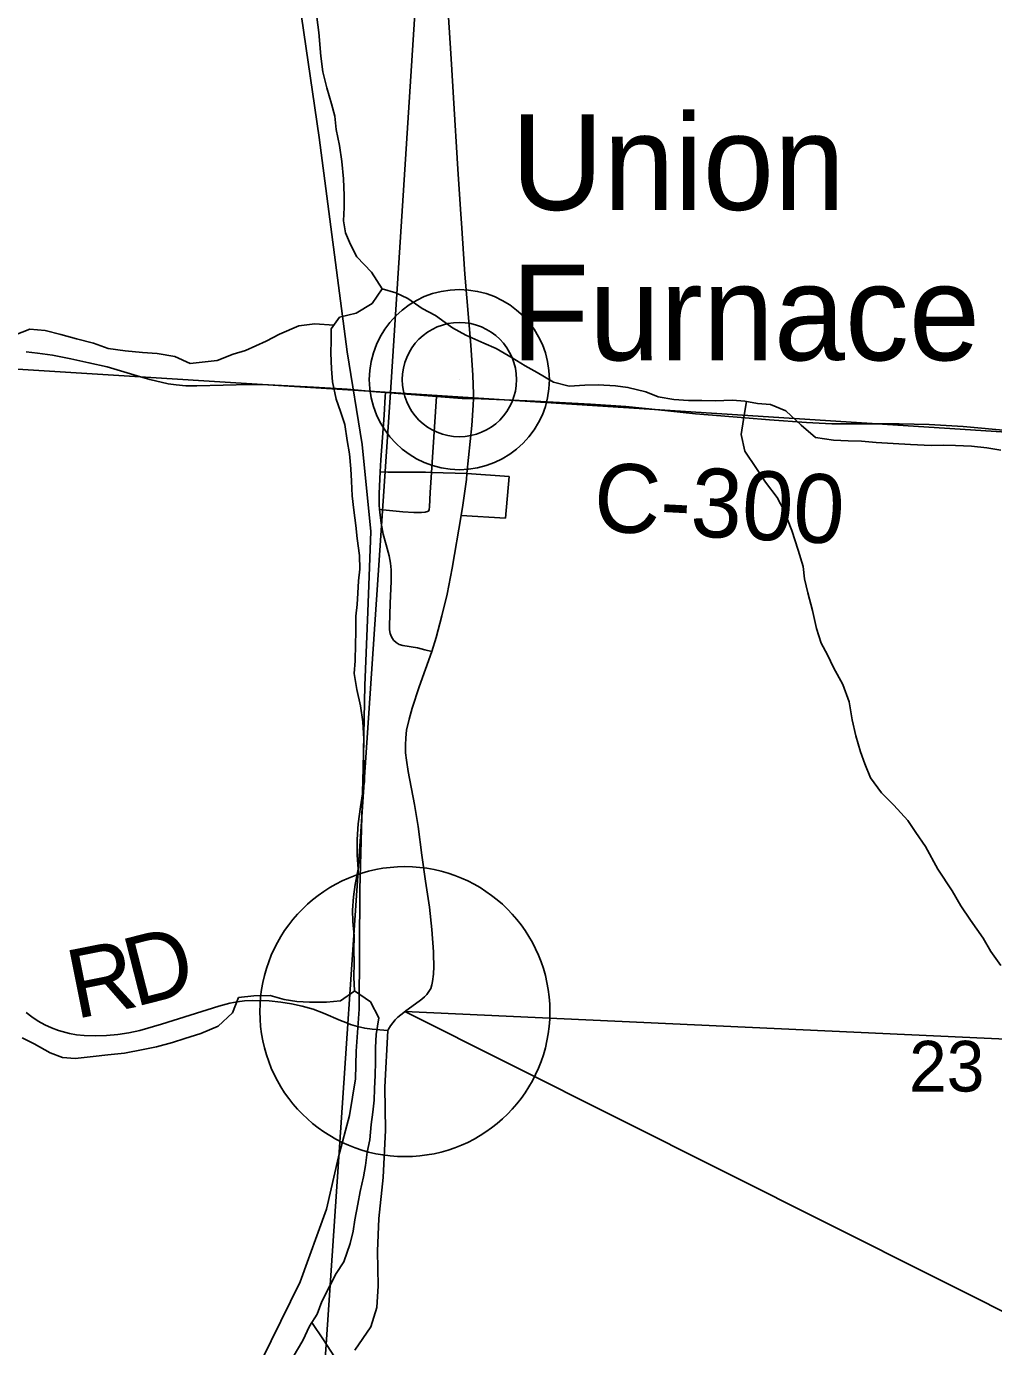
# Model space of a CAD drawing. Extents: x 0 to 34, y 0 to 22.
# Drawn here: x 5.158 to 5.957, y 17.019 to 18.11 of the extents above; entities that cross this region are included whole.
import ezdxf

# ---------------------------------------------------------------- set-up
doc = ezdxf.new("R2010")
doc.units = 0
for name, color, linetype in [('Default', 7, 'Continuous'), ('GM_X_Corporation', 7, 'Continuous'), ('GM_X_County_Road', 7, 'Continuous'), ('GM_X_County_Road_Text', 7, 'Continuous'), ('GM_X_Minor_River', 7, 'Continuous'), ('GM_X_Rail_Line', 7, 'Continuous'), ('GM_X_Section_Text', 7, 'Continuous'), ('GM_X_State_Route', 7, 'Continuous'), ('GM_X_Township_Road', 7, 'Continuous'), ('GM_X_Township_Road_Text', 7, 'Continuous'), ('GM_X_Unincorporated', 7, 'Continuous'), ('GM_X_Unincorporated_Location', 7, 'Continuous'), ('GM_X_Unincorporated_Text', 7, 'Continuous'), ('SH_Text', 7, 'Continuous')]:
    doc.layers.add(name, color=color, linetype=linetype)

msp = doc.modelspace()

# ---------------------------------------------------------------- linework, layer by layer
at = {"layer": 'Default'}
msp.add_circle((5.4711, 17.2956), 0.1198, dxfattribs=at)
at = {"layer": 'GM_X_Corporation'}
for points in [[(4.5309, 18.9179), (5.5263, 18.8526), (5.4592, 17.8072), (4.4596, 17.8697), (4.5247, 18.9179)], [(6.5391, 18.7835), (6.4386, 17.7441), (5.4592, 17.8072), (5.5263, 18.8526)], [(4.4596, 17.8697), (5.4592, 17.8072), (5.3901, 16.7843), (4.3853, 16.8539)], [(6.4386, 17.7441), (6.3912, 16.7203), (5.3901, 16.7843), (5.4592, 17.8072)]]:
    msp.add_lwpolyline(points, close=True, dxfattribs=at)
at = {"layer": 'GM_X_County_Road'}
for points in [[(5.1583, 17.8407), (5.1676, 17.8397), (5.1799, 17.8379), (5.195, 17.835), (5.2101, 17.8317), (5.2251, 17.8282), (5.2498, 17.8207), (5.2604, 17.8177), (5.2756, 17.8142), (5.2821, 17.8133), (5.2902, 17.8127), (5.2993, 17.8126), (5.3428, 17.8137), (5.3583, 17.8135), (5.3956, 17.8116), (5.419, 17.81), (5.4235, 17.8097), (5.4473, 17.8077)], [(5.4473, 17.8077), (5.4512, 17.8074), (5.4551, 17.8071), (5.4938, 17.804), (5.4973, 17.8037), (5.5185, 17.8022), (5.5216, 17.8022), (5.5277, 17.8021)], [(5.5277, 17.8021), (5.5781, 17.8), (5.6245, 17.7974), (5.6536, 17.7954), (5.6806, 17.7927), (5.7113, 17.7895), (5.732, 17.7877), (5.7722, 17.7846), (5.803, 17.7822), (5.8239, 17.7811), (5.8577, 17.7812), (5.8794, 17.7813), (5.9043, 17.7807), (5.9322, 17.7789), (5.9713, 17.7755)]]:
    msp.add_lwpolyline(points, dxfattribs=at)
at = {"layer": 'GM_X_Minor_River'}
for p, q in [((5.1612, 17.8595), (5.1487, 17.8544)), ((5.174, 17.8584), (5.1612, 17.8595)), ((5.1869, 17.8551), (5.174, 17.8584)), ((5.1998, 17.8515), (5.1869, 17.8551)), ((5.3674, 17.8553), (5.3565, 17.8495)), ((5.3836, 17.8622), (5.3674, 17.8553)), ((5.3968, 17.8639), (5.3836, 17.8622)), ((5.4124, 17.8628), (5.3968, 17.8639)), ((5.2139, 17.8478), (5.1998, 17.8515)), ((5.226, 17.8434), (5.2139, 17.8478)), ((5.24, 17.8416), (5.226, 17.8434)), ((5.3565, 17.8495), (5.3395, 17.8418)), ((5.2544, 17.8402), (5.24, 17.8416)), ((5.2665, 17.8392), (5.2544, 17.8402)), ((5.2809, 17.8367), (5.2665, 17.8392)), ((5.2938, 17.8311), (5.2809, 17.8367)), ((5.3037, 17.832), (5.2938, 17.8311)), ((5.3161, 17.8336), (5.3037, 17.832)), ((5.3293, 17.8386), (5.3161, 17.8336)), ((5.3395, 17.8418), (5.3293, 17.8386)), ((5.7532, 17.7998), (5.7509, 17.7849)), ((5.7509, 17.7849), (5.7488, 17.7723)), ((5.7488, 17.7723), (5.7519, 17.7587)), ((5.7519, 17.7587), (5.7615, 17.7444)), ((5.7615, 17.7444), (5.7691, 17.7331)), ((5.7691, 17.7331), (5.7787, 17.7203)), ((5.7787, 17.7203), (5.7841, 17.7098)), ((5.7841, 17.7098), (5.7907, 17.6931)), ((5.7907, 17.6931), (5.7961, 17.6769)), ((5.7961, 17.6769), (5.8, 17.6633)), ((5.8, 17.6633), (5.8012, 17.6531)), ((5.8012, 17.6531), (5.804, 17.6417)), ((5.804, 17.6417), (5.8079, 17.627)), ((5.8079, 17.627), (5.8111, 17.6122)), ((5.8111, 17.6122), (5.815, 17.6001)), ((5.815, 17.6001), (5.8203, 17.5903)), ((5.8203, 17.5903), (5.8253, 17.5798)), ((5.8253, 17.5798), (5.833, 17.5658)), ((5.833, 17.5658), (5.8381, 17.5515)), ((5.8381, 17.5515), (5.8405, 17.5367)), ((5.8405, 17.5367), (5.8436, 17.5235)), ((5.8436, 17.5235), (5.8475, 17.5102)), ((5.8475, 17.5102), (5.851, 17.5004)), ((5.851, 17.5004), (5.8557, 17.4887)), ((5.8557, 17.4887), (5.8648, 17.4763)), ((5.8648, 17.4763), (5.8751, 17.4662)), ((5.8751, 17.4662), (5.8866, 17.4534)), ((5.8866, 17.4534), (5.8931, 17.4436)), ((5.8931, 17.4436), (5.9012, 17.4319)), ((5.9012, 17.4319), (5.9115, 17.4134)), ((5.9115, 17.4134), (5.9231, 17.3954)), ((5.9231, 17.3954), (5.9304, 17.3829)), ((5.9304, 17.3829), (5.9384, 17.3712)), ((5.9384, 17.3712), (5.9487, 17.3562)), ((5.9487, 17.3562), (5.9553, 17.3453)), ((5.9553, 17.3453), (5.9633, 17.3336)), ((5.3464, 17.3086), (5.3336, 17.3074)), ((5.3597, 17.3088), (5.3464, 17.3086)), ((5.3714, 17.3055), (5.3597, 17.3088)), ((5.4297, 17.3128), (5.418, 17.3044)), ((5.3336, 17.3074), (5.3288, 17.2945)), ((5.3817, 17.304), (5.3714, 17.3055)), ((5.3923, 17.3034), (5.3817, 17.304)), ((5.4063, 17.3035), (5.3923, 17.3034)), ((5.418, 17.3044), (5.4063, 17.3035)), ((5.3288, 17.2945), (5.3168, 17.2837)), ((5.3024, 17.2775), (5.2892, 17.2733)), ((5.3168, 17.2837), (5.3024, 17.2775)), ((5.1648, 17.2691), (5.1549, 17.2739)), ((5.1781, 17.2616), (5.1648, 17.2691)), ((5.2658, 17.2666), (5.2549, 17.2642)), ((5.279, 17.2701), (5.2658, 17.2666)), ((5.2892, 17.2733), (5.279, 17.2701)), ((5.1883, 17.2576), (5.1781, 17.2616)), ((5.1986, 17.2569), (5.1883, 17.2576)), ((5.2137, 17.2586), (5.1986, 17.2569)), ((5.2258, 17.2598), (5.2137, 17.2586)), ((5.2394, 17.2614), (5.2258, 17.2598)), ((5.2549, 17.2642), (5.2394, 17.2614)), ((5.3942, 17.0387), (5.4038, 17.0246)), ((5.4038, 17.0246), (5.413, 17.0103))]:
    msp.add_line(p, q, dxfattribs=at)
for points in [[(5.3984, 18.117), (5.4, 18.1045), (5.4017, 18.0848), (5.4034, 18.072), (5.4065, 18.0587), (5.4104, 18.0455), (5.4131, 18.0353), (5.4144, 18.0243), (5.4171, 18.0111), (5.4191, 17.9978), (5.4204, 17.9835), (5.4209, 17.9698), (5.421, 17.96), (5.4203, 17.949), (5.4219, 17.9391), (5.4262, 17.9293), (5.4315, 17.9191), (5.4434, 17.9064), (5.4522, 17.8928), (5.444, 17.8806), (5.4308, 17.8725), (5.4172, 17.8694), (5.4101, 17.8598), (5.4102, 17.85), (5.4099, 17.8397), (5.4104, 17.8265), (5.4113, 17.8159), (5.4144, 17.8015), (5.4179, 17.7913), (5.4214, 17.7807), (5.4234, 17.7675), (5.4254, 17.7565), (5.4263, 17.744), (5.4271, 17.7338), (5.4276, 17.7217), (5.4288, 17.7099), (5.4305, 17.6971), (5.4317, 17.6865), (5.4337, 17.6725), (5.4338, 17.6611), (5.4327, 17.6516), (5.4321, 17.6414), (5.4318, 17.6319), (5.4307, 17.6224), (5.4305, 17.6091), (5.4302, 17.5993), (5.4299, 17.5853), (5.4292, 17.575), (5.4313, 17.5618), (5.4344, 17.5482), (5.4364, 17.5349), (5.4373, 17.5209), (5.437, 17.5061), (5.4375, 17.4955), (5.4376, 17.4853), (5.4362, 17.4754), (5.4344, 17.4648), (5.4326, 17.4508), (5.4316, 17.4379), (5.4317, 17.425)], [(5.4522, 17.8928), (5.4636, 17.8895), (5.4735, 17.8847), (5.4853, 17.8764), (5.4963, 17.8708), (5.5104, 17.8604), (5.5214, 17.8544), (5.5362, 17.8477), (5.5465, 17.8433), (5.5598, 17.8358), (5.5704, 17.8291), (5.5803, 17.8235), (5.594, 17.8156), (5.6069, 17.8124), (5.6198, 17.8132), (5.6307, 17.8133), (5.6451, 17.8127), (5.6553, 17.8113), (5.6701, 17.8076), (5.6804, 17.8035), (5.6933, 17.8014), (5.7054, 17.8004), (5.7163, 17.8005), (5.7273, 17.8002), (5.7417, 17.8007), (5.7519, 17.8), (5.7625, 17.7979), (5.7731, 17.7972), (5.7857, 17.792), (5.7986, 17.78), (5.8104, 17.7699), (5.8252, 17.7677), (5.8373, 17.7671), (5.8483, 17.7668), (5.8604, 17.7658), (5.8744, 17.7648), (5.8888, 17.7641), (5.9059, 17.7632), (5.9161, 17.7636), (5.9259, 17.7633), (5.9392, 17.7627), (5.952, 17.7613), (5.9634, 17.7595)], [(5.4317, 17.425), (5.4325, 17.4133), (5.43, 17.4007), (5.4286, 17.3905), (5.4279, 17.3795), (5.428, 17.37), (5.4292, 17.3583), (5.429, 17.3465), (5.4291, 17.3363), (5.4288, 17.3242), (5.4296, 17.3128), (5.4426, 17.3038), (5.4495, 17.2906), (5.4474, 17.2766), (5.4467, 17.266), (5.4468, 17.2542), (5.4465, 17.2432), (5.4459, 17.2319), (5.4456, 17.2224), (5.4445, 17.2125), (5.4431, 17.2023), (5.4421, 17.1898), (5.4399, 17.1795), (5.4385, 17.1685), (5.437, 17.159), (5.4341, 17.1469), (5.4323, 17.1366), (5.4298, 17.1237), (5.4283, 17.1142), (5.4258, 17.104), (5.4206, 17.0888), (5.4143, 17.0792), (5.4091, 17.069), (5.4024, 17.056), (5.3987, 17.0458), (5.3923, 17.0358), (5.3867, 17.024), (5.3789, 17.0103)]]:
    msp.add_lwpolyline(points, dxfattribs=at)
at = {"layer": 'GM_X_Rail_Line'}
msp.add_lwpolyline([(5.3526, 17.0073), (5.3847, 17.0725), (5.4062, 17.1325), (5.4163, 17.1756), (5.4252, 17.2099), (5.4302, 17.24), (5.4309, 17.2629), (5.4333, 17.2975), (5.4338, 17.3964), (5.4367, 17.4966), (5.4381, 17.5651), (5.4404, 17.626), (5.443, 17.6922), (5.4357, 17.7642), (5.4234, 17.8408), (5.4004, 18.0178), (5.3565, 18.3179)], dxfattribs=at)
at = {"layer": 'GM_X_State_Route'}
for points in [[(5.5112, 18.0505), (5.5095, 18.0784), (5.5026, 18.1868), (5.496, 18.2766), (5.4945, 18.2921), (5.4928, 18.3043), (5.4911, 18.3134), (5.4889, 18.3224), (5.4881, 18.3254), (5.4872, 18.3284)], [(5.4947, 17.343), (5.4947, 17.3451), (5.4934, 17.3634), (5.4914, 17.3819), (5.4882, 17.4034), (5.4852, 17.4249), (5.4821, 17.4485), (5.4791, 17.4666), (5.4737, 17.494), (5.4723, 17.5032), (5.4717, 17.5094), (5.4716, 17.5156), (5.4718, 17.5219), (5.4725, 17.5281), (5.4745, 17.5373), (5.477, 17.5463), (5.4829, 17.564), (5.4933, 17.5931), (5.497, 17.6048), (5.5017, 17.6225), (5.5059, 17.6406), (5.5101, 17.6619), (5.5176, 17.7054), (5.519, 17.7139), (5.5219, 17.7353), (5.5224, 17.7401), (5.5264, 17.7799), (5.5276, 17.7965), (5.5277, 17.8021), (5.5278, 17.8057), (5.5272, 17.8213), (5.5256, 17.8461), (5.5207, 17.9048), (5.5178, 17.947), (5.5172, 17.9544), (5.5147, 17.9916), (5.5112, 18.0505)], [(5.4297, 17.016), (5.4429, 17.0352), (5.4479, 17.0511), (5.4491, 17.069), (5.4484, 17.0978), (5.4496, 17.1247), (5.4531, 17.1585), (5.4551, 17.1976), (5.4545, 17.2332), (5.457, 17.2801), (5.4575, 17.2812), (5.4592, 17.2839), (5.4631, 17.2888), (5.4654, 17.2911), (5.4703, 17.295), (5.472, 17.2962), (5.4828, 17.3042), (5.4851, 17.306), (5.4872, 17.3077), (5.4893, 17.3098), (5.491, 17.3122), (5.4924, 17.3148), (5.4934, 17.3176), (5.494, 17.3206), (5.4948, 17.3266), (5.495, 17.3328), (5.4947, 17.343)]]:
    msp.add_lwpolyline(points, dxfattribs=at)
at = {"layer": 'GM_X_Township_Road'}
msp.add_line((5.5224, 17.7401), (5.5572, 17.7376), dxfattribs=at)
for points in [[(5.4532, 17.69), (5.4515, 17.6991), (5.4503, 17.7083), (5.4502, 17.7104), (5.4499, 17.7144), (5.4499, 17.7237), (5.4507, 17.7414), (5.4512, 17.7515), (5.4539, 17.7884), (5.4549, 17.8038), (5.4551, 17.8071)], [(5.4907, 17.7091), (5.4911, 17.7103), (5.4913, 17.7125), (5.4921, 17.7244), (5.493, 17.741), (5.497, 17.7997), (5.4973, 17.8037)], [(5.4507, 17.7414), (5.4571, 17.7413), (5.4881, 17.7412), (5.493, 17.741), (5.5224, 17.7401)], [(5.5176, 17.7054), (5.5542, 17.7033), (5.5572, 17.7376)], [(5.4502, 17.7104), (5.4693, 17.7085), (5.4785, 17.7078), (5.4847, 17.7079), (5.4878, 17.7082), (5.4907, 17.7091)], [(5.4933, 17.5931), (5.4876, 17.5945), (5.4816, 17.596), (5.4695, 17.5981), (5.4665, 17.599), (5.4638, 17.6005), (5.4616, 17.6026), (5.4599, 17.6052), (5.4589, 17.6081), (5.4585, 17.6111), (5.4585, 17.6142), (5.459, 17.6327), (5.4597, 17.6512), (5.4597, 17.6605), (5.4592, 17.6662), (5.4581, 17.6722), (5.4556, 17.6811), (5.4532, 17.69)], [(5.1581, 17.295), (5.1629, 17.2912), (5.168, 17.2877), (5.1735, 17.2847), (5.1791, 17.2822), (5.185, 17.2801), (5.1939, 17.2776), (5.1999, 17.2765), (5.2061, 17.2758), (5.2153, 17.2756), (5.2246, 17.2759), (5.2339, 17.2768), (5.2431, 17.2781), (5.2522, 17.28), (5.2701, 17.2852), (5.3174, 17.3002), (5.3264, 17.3026), (5.3325, 17.3038), (5.3386, 17.3044), (5.3451, 17.3048), (5.3591, 17.3045), (5.3685, 17.3033), (5.3775, 17.302), (5.3863, 17.3001), (5.3952, 17.2975), (5.4039, 17.2943), (5.418, 17.2883), (5.4224, 17.2865), (5.4262, 17.285), (5.4319, 17.2833), (5.4379, 17.2819), (5.4441, 17.281), (5.4503, 17.2806), (5.457, 17.2801)]]:
    msp.add_lwpolyline(points, dxfattribs=at)
at = {"layer": 'GM_X_Unincorporated'}
for radius in [0.0744, 0.0472]:
    msp.add_circle((5.5161, 17.8177), radius, dxfattribs=at)
at = {"layer": 'GM_X_Unincorporated_Location'}
msp.add_line((5.5161, 17.8177), (5.5161, 17.8177), dxfattribs=at)
at = {"layer": 'SH_Text'}
msp.add_lwpolyline([(5.4711, 17.2956), (5.9977, 17.2715), (5.9977, 17.0315)], close=True, dxfattribs=at)

# ---------------------------------------------------------------- texts
at = {"layer": 'GM_X_County_Road_Text'}
msp.add_text('C-300', height=0.05682, rotation=356.9734, dxfattribs=at).set_placement((5.6261, 17.6927))
at = {"layer": 'GM_X_Section_Text'}
msp.add_text('23', height=0.04186, rotation=0, dxfattribs=at).set_placement((5.8876, 17.2296))
at = {"layer": 'GM_X_Township_Road_Text'}
for s, rotation, p in [('D', 14.3237, (5.2479, 17.2993)), ('R', 11.2617, (5.199, 17.2894))]:
    msp.add_text(s, height=0.0568, rotation=rotation, dxfattribs=at).set_placement(p)
at = {"layer": 'GM_X_Unincorporated_Text'}
for s, p in [('Union', (5.5588, 17.9579)), ('Furnace', (5.5588, 17.8337))]:
    msp.add_text(s, height=0.07898, rotation=0, dxfattribs=at).set_placement(p)

doc.saveas('drawing.dxf')
